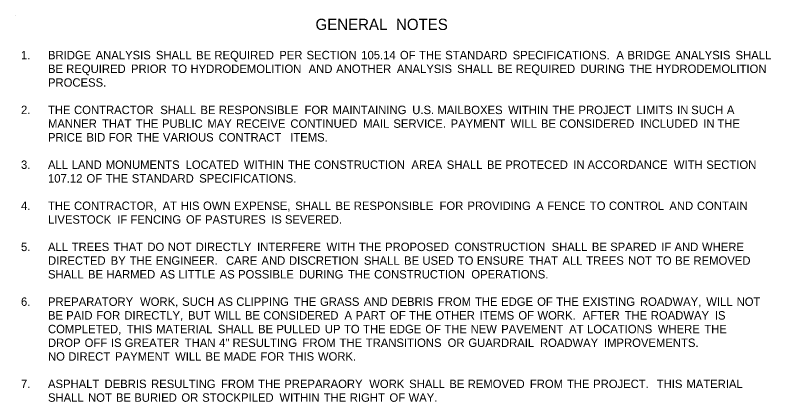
# Model space of a CAD drawing. Extents: x 1930579 to 1935779, y 596313 to 597298.
# Drawn here: x 1934270 to 1934916, y 596918 to 597248 of the extents above; entities that cross this region are included whole.
import ezdxf

# ---------------------------------------------------------------- set-up
doc = ezdxf.new("R2010")
doc.units = 0
doc.layers.add('Default', color=7, linetype='Continuous')
doc.layers.add('R_Border', color=7, linetype='Continuous')

msp = doc.modelspace()

# ---------------------------------------------------------------- linework, layer by layer
at = {"layer": 'R_Border'}
msp.add_line((1934270.13, 597248.45), (1934270.13, 597248.45), dxfattribs=at)

# ---------------------------------------------------------------- texts
at = {"layer": 'Default'}
for s, height, p in [('GENERAL', 9.6, (1934526.75, 597235.75)), (' NOTES', 9.6, (1934591.93, 597235.75)), ('1.', 7.2, (1934275.15, 597210.7)), ('BRIDGE', 7.2, (1934298.21, 597210.7)), (' ANALYSIS', 7.2, (1934336.24, 597210.7)), (' SHALL', 7.2, (1934387.72, 597210.7)), (' BE', 7.2, (1934422.03, 597210.7)), (' REQUIRED', 7.2, (1934437.71, 597210.7)), (' PER', 7.2, (1934493.07, 597210.7)), (' SECTION', 7.2, (1934516.41, 597210.7)), (' 105.14', 7.2, (1934563.1, 597210.7)), (' OF', 7.2, (1934596.16, 597210.7)), (' THE', 7.2, (1934612.47, 597210.7)), (' STANDARD', 7.2, (1934634.85, 597210.7)), (' SPECIFICATIONS.', 7.2, (1934692.45, 597210.7)), (' A', 7.2, (1934781.01, 597210.7)), (' BRIDGE', 7.2, (1934790.53, 597210.7)), (' ANALYSIS', 7.2, (1934831.36, 597210.7)), (' SHALL', 7.2, (1934882.84, 597210.7)), ('BE', 7.2, (1934298.21, 597199)), (' REQUIRED', 7.2, (1934311.09, 597199)), (' PRIOR', 7.2, (1934366.45, 597199)), (' TO', 7.2, (1934400.97, 597199)), (' HYDRODEMOLITION', 7.2, (1934417.29, 597199)), (' AND', 7.2, (1934518.19, 597199)), (' ANOTHER', 7.2, (1934541.69, 597199)), (' ANALYSIS', 7.2, (1934593.54, 597199)), (' SHALL', 7.2, (1934645.02, 597199)), (' BE', 7.2, (1934679.33, 597199)), (' REQUIRED', 7.2, (1934695, 597199)), (' DURING', 7.2, (1934750.37, 597199)), (' THE', 7.2, (1934792.21, 597199)), (' HYDRODEMOLITION', 7.2, (1934814.59, 597199)), ('PROCESS.', 7.2, (1934298.21, 597187.3)), ('2.', 7.2, (1934275.15, 597163.9)), ('THE', 7.2, (1934298.21, 597163.9)), (' CONTRACTOR', 7.2, (1934317.79, 597163.9)), (' SHALL', 7.2, (1934391.44, 597163.9)), (' BE', 7.2, (1934425.75, 597163.9)), (' RESPONSIBLE', 7.2, (1934441.42, 597163.9)), (' FOR', 7.2, (1934514.69, 597163.9)), (' MAINTAINING', 7.2, (1934538.59, 597163.9)), (' U.S.', 7.2, (1934606.7, 597163.9)), (' MAILBOXES', 7.2, (1934628.18, 597163.9)), (' WITHIN', 7.2, (1934688.59, 597163.9)), (' THE', 7.2, (1934726.32, 597163.9)), (' PROJECT', 7.2, (1934748.7, 597163.9)), (' LIMITS', 7.2, (1934798.25, 597163.9)), (' IN', 7.2, (1934832.93, 597163.9)), (' SUCH', 7.2, (1934844.96, 597163.9)), (' A', 7.2, (1934875.45, 597163.9)), ('MANNER', 7.2, (1934298.21, 597152.2)), (' THAT', 7.2, (1934341.67, 597152.2)), (' THE', 7.2, (1934370.53, 597152.2)), (' PUBLIC', 7.2, (1934392.91, 597152.2)), (' MAY', 7.2, (1934431.64, 597152.2)), (' RECEIVE', 7.2, (1934456.16, 597152.2)), (' CONTINUED', 7.2, (1934502.59, 597152.2)), (' MAIL', 7.2, (1934564.65, 597152.2)), (' SERVICE.', 7.2, (1934590.57, 597152.2)), (' PAYMENT', 7.2, (1934639.45, 597152.2)), (' WILL', 7.2, (1934690.67, 597152.2)), (' BE', 7.2, (1934716.58, 597152.2)), (' CONSIDERED', 7.2, (1934732.26, 597152.2)), (' INCLUDED', 7.2, (1934801.6, 597152.2)), (' IN', 7.2, (1934855.28, 597152.2)), (' THE', 7.2, (1934867.31, 597152.2)), ('PRICE', 7.2, (1934298.21, 597140.5)), (' BID', 7.2, (1934328.42, 597140.5)), (' FOR', 7.2, (1934347.45, 597140.5)), (' THE', 7.2, (1934371.34, 597140.5)), (' VARIOUS', 7.2, (1934393.72, 597140.5)), (' CONTRACT', 7.2, (1934441.27, 597140.5)), ('  ITEMS.', 7.2, (1934499.75, 597140.5)), ('3.', 7.2, (1934275.15, 597117.1)), ('ALL', 7.2, (1934298.21, 597117.1)), (' LAND', 7.2, (1934315.75, 597117.1)), (' MONUMENTS', 7.2, (1934344.84, 597117.1)), (' LOCATED', 7.2, (1934413.06, 597117.1)), (' WITHIN', 7.2, (1934462.83, 597117.1)), (' THE', 7.2, (1934500.56, 597117.1)), (' CONSTRUCTION', 7.2, (1934522.94, 597117.1)), (' AREA', 7.2, (1934605.95, 597117.1)), (' SHALL', 7.2, (1934636.16, 597117.1)), (' BE', 7.2, (1934670.47, 597117.1)), (' PROTECED', 7.2, (1934686.15, 597117.1)), (' IN', 7.2, (1934744.31, 597117.1)), (' ACCORDANCE', 7.2, (1934756.34, 597117.1)), (' WITH', 7.2, (1934830.15, 597117.1)), (' SECTION', 7.2, (1934857.83, 597117.1)), ('107.12', 7.2, (1934298.21, 597105.4)), (' OF', 7.2, (1934328.43, 597105.4)), (' THE', 7.2, (1934344.73, 597105.4)), (' STANDARD', 7.2, (1934367.11, 597105.4)), (' SPECIFICATIONS.', 7.2, (1934424.71, 597105.4)), ('4.', 7.2, (1934275.15, 597082)), ('THE', 7.2, (1934298.21, 597082)), (' CONTRACTOR,', 7.2, (1934317.79, 597082)), (' AT', 7.2, (1934393.47, 597082)), (' HIS', 7.2, (1934408.92, 597082)), (' OWN', 7.2, (1934427.96, 597082)), (' EXPENSE,', 7.2, (1934454.51, 597082)), (' SHALL', 7.2, (1934506.74, 597082)), (' BE', 7.2, (1934541.05, 597082)), (' RESPONSIBLE', 7.2, (1934556.73, 597082)), (' FOR', 7.2, (1934630, 597082)), (' PROVIDING', 7.2, (1934653.89, 597082)), (' A', 7.2, (1934712.51, 597082)), (' FENCE', 7.2, (1934722.03, 597082)), (' TO', 7.2, (1934758.39, 597082)), (' CONTROL', 7.2, (1934774.7, 597082)), (' AND', 7.2, (1934826.33, 597082)), (' CONTAIN', 7.2, (1934849.83, 597082)), ('LIVESTOCK', 7.2, (1934298.21, 597070.3)), (' IF', 7.2, (1934354.66, 597070.3)), (' FENCING', 7.2, (1934365.93, 597070.3)), (' OF', 7.2, (1934413.36, 597070.3)), (' PASTURES', 7.2, (1934429.67, 597070.3)), (' IS', 7.2, (1934486.17, 597070.3)), (' SEVERED.', 7.2, (1934497.94, 597070.3)), ('5.', 7.2, (1934275.15, 597046.9)), ('ALL', 7.2, (1934298.21, 597046.9)), (' TREES', 7.2, (1934315.75, 597046.9)), (' THAT', 7.2, (1934351.56, 597046.9)), (' DO', 7.2, (1934380.42, 597046.9)), (' NOT', 7.2, (1934397.86, 597046.9)), (' DIRECTLY', 7.2, (1934421.68, 597046.9)), (' INTERFERE', 7.2, (1934474.15, 597046.9)), (' WITH', 7.2, (1934533.43, 597046.9)), (' THE', 7.2, (1934561.11, 597046.9)), (' PROPOSED', 7.2, (1934583.49, 597046.9)), (' CONSTRUCTION', 7.2, (1934642.77, 597046.9)), (' SHALL', 7.2, (1934725.79, 597046.9)), (' BE', 7.2, (1934760.1, 597046.9)), (' SPARED', 7.2, (1934775.77, 597046.9)), (' IF', 7.2, (1934819.41, 597046.9)), (' AND', 7.2, (1934830.68, 597046.9)), (' WHERE', 7.2, (1934854.18, 597046.9)), ('DIRECTED', 7.2, (1934298.21, 597035.2)), (' BY', 7.2, (1934349.1, 597035.2)), (' THE', 7.2, (1934365.24, 597035.2)), (' ENGINEER.', 7.2, (1934387.62, 597035.2)), ('  CARE', 7.2, (1934444.88, 597035.2)), (' AND', 7.2, (1934477.88, 597035.2)), (' DISCRETION', 7.2, (1934501.38, 597035.2)), (' SHALL', 7.2, (1934565.39, 597035.2)), (' BE', 7.2, (1934599.7, 597035.2)), (' USED', 7.2, (1934615.38, 597035.2)), (' TO', 7.2, (1934645.59, 597035.2)), (' ENSURE', 7.2, (1934661.91, 597035.2)), (' THAT', 7.2, (1934706.1, 597035.2)), (' ALL', 7.2, (1934734.96, 597035.2)), (' TREES', 7.2, (1934755.29, 597035.2)), (' NOT', 7.2, (1934791.1, 597035.2)), (' TO', 7.2, (1934814.93, 597035.2)), (' BE', 7.2, (1934831.24, 597035.2)), (' REMOVED', 7.2, (1934846.92, 597035.2)), ('SHALL', 7.2, (1934298.21, 597023.5)), (' BE', 7.2, (1934329.73, 597023.5)), (' HARMED', 7.2, (1934345.4, 597023.5)), (' AS', 7.2, (1934391.26, 597023.5)), (' LITTLE', 7.2, (1934406.95, 597023.5)), (' AS', 7.2, (1934442.19, 597023.5)), (' POSSIBLE', 7.2, (1934457.88, 597023.5)), (' DURING', 7.2, (1934509.9, 597023.5)), (' THE', 7.2, (1934551.75, 597023.5)), (' CONSTRUCTION', 7.2, (1934574.12, 597023.5)), (' OPERATIONS.', 7.2, (1934657.14, 597023.5)), ('6.', 7.2, (1934275.15, 597000.1)), ('PREPARATORY', 7.2, (1934298.21, 597000.1)), (' WORK,', 7.2, (1934374.17, 597000.1)), (' SUCH', 7.2, (1934410.16, 597000.1)), (' AS', 7.2, (1934440.65, 597000.1)), (' CLIPPING', 7.2, (1934456.34, 597000.1)), (' THE', 7.2, (1934505.46, 597000.1)), (' GRASS', 7.2, (1934527.84, 597000.1)), (' AND', 7.2, (1934565.33, 597000.1)), (' DEBRIS', 7.2, (1934588.83, 597000.1)), (' FROM', 7.2, (1934628.56, 597000.1)), (' THE', 7.2, (1934660.21, 597000.1)), (' EDGE', 7.2, (1934682.59, 597000.1)), (' OF', 7.2, (1934713.36, 597000.1)), (' THE', 7.2, (1934729.67, 597000.1)), (' EXISTING', 7.2, (1934752.04, 597000.1)), (' ROADWAY,', 7.2, (1934801.17, 597000.1)), (' WILL', 7.2, (1934857.84, 597000.1)), (' NOT', 7.2, (1934883.75, 597000.1)), ('BE', 7.2, (1934298.21, 596988.4)), (' PAID', 7.2, (1934311.09, 596988.4)), (' FOR', 7.2, (1934336.83, 596988.4)), (' DIRECTLY,', 7.2, (1934360.73, 596988.4)), (' BUT', 7.2, (1934415.17, 596988.4)), (' WILL', 7.2, (1934437.88, 596988.4)), (' BE', 7.2, (1934463.79, 596988.4)), (' CONSIDERED', 7.2, (1934479.47, 596988.4)), (' A', 7.2, (1934548.81, 596988.4)), (' PART', 7.2, (1934558.33, 596988.4)), (' OF', 7.2, (1934587.76, 596988.4)), (' THE', 7.2, (1934604.06, 596988.4)), (' OTHER', 7.2, (1934626.44, 596988.4)), (' ITEMS', 7.2, (1934664.31, 596988.4)), (' OF', 7.2, (1934697.32, 596988.4)), (' WORK.', 7.2, (1934713.62, 596988.4)), ('  AFTER', 7.2, (1934749.63, 596988.4)), (' THE', 7.2, (1934788.06, 596988.4)), (' ROADWAY', 7.2, (1934810.44, 596988.4)), (' IS', 7.2, (1934865.14, 596988.4)), ('COMPLETED,', 7.2, (1934298.21, 596976.7)), (' THIS', 7.2, (1934362.72, 596976.7)), (' MATERIAL', 7.2, (1934387.9, 596976.7)), (' SHALL', 7.2, (1934440.65, 596976.7)), (' BE', 7.2, (1934474.96, 596976.7)), (' PULLED', 7.2, (1934490.64, 596976.7)), (' UP', 7.2, (1934532.03, 596976.7)), (' TO', 7.2, (1934548.36, 596976.7)), (' THE', 7.2, (1934564.68, 596976.7)), (' EDGE', 7.2, (1934587.06, 596976.7)), (' OF', 7.2, (1934617.83, 596976.7)), (' THE', 7.2, (1934634.13, 596976.7)), (' NEW', 7.2, (1934656.51, 596976.7)), (' PAVEMENT', 7.2, (1934682.66, 596976.7)), (' AT', 7.2, (1934740.6, 596976.7)), (' LOCATIONS', 7.2, (1934756.05, 596976.7)), (' WHERE', 7.2, (1934816.45, 596976.7)), (' THE', 7.2, (1934856.16, 596976.7)), ('DROP', 7.2, (1934298.21, 596965)), (' OFF', 7.2, (1934326.84, 596965)), (' IS', 7.2, (1934349.29, 596965)), (' GREATER', 7.2, (1934361.06, 596965)), (' THAN', 7.2, (1934412.35, 596965)), (' 4"', 7.2, (1934441.71, 596965)), (' RESULTING', 7.2, (1934453.2, 596965)), (' FROM', 7.2, (1934512.94, 596965)), (' THE', 7.2, (1934544.59, 596965)), (' TRANSITIONS', 7.2, (1934566.97, 596965)), (' OR', 7.2, (1934636.88, 596965)), (' GUARDRAIL', 7.2, (1934654.63, 596965)), (' ROADWAY', 7.2, (1934715.76, 596965)), (' IMPROVEMENTS.', 7.2, (1934770.46, 596965)), ('NO', 7.2, (1934298.21, 596953.3)), (' DIRECT', 7.2, (1934312.85, 596953.3)), (' PAYMENT', 7.2, (1934352.89, 596953.3)), (' WILL', 7.2, (1934404.12, 596953.3)), (' BE', 7.2, (1934430.03, 596953.3)), (' MADE', 7.2, (1934445.7, 596953.3)), (' FOR', 7.2, (1934477.03, 596953.3)), (' THIS', 7.2, (1934500.92, 596953.3)), (' WORK.', 7.2, (1934526.11, 596953.3)), ('7.', 7.2, (1934275.15, 596929.9)), ('ASPHALT', 7.2, (1934298.21, 596929.9)), (' DEBRIS', 7.2, (1934343.86, 596929.9)), (' RESULTING', 7.2, (1934383.58, 596929.9)), (' FROM', 7.2, (1934443.32, 596929.9)), (' THE', 7.2, (1934474.98, 596929.9)), (' PREPARAORY', 7.2, (1934497.36, 596929.9)), (' WORK', 7.2, (1934569.96, 596929.9)), (' SHALL', 7.2, (1934604.03, 596929.9)), (' BE', 7.2, (1934638.34, 596929.9)), (' REMOVED', 7.2, (1934654.02, 596929.9)), (' FROM', 7.2, (1934707.15, 596929.9)), (' THE', 7.2, (1934738.8, 596929.9)), (' PROJECT.', 7.2, (1934761.18, 596929.9)), ('  THIS', 7.2, (1934812.85, 596929.9)), (' MATERIAL', 7.2, (1934840.83, 596929.9)), ('SHALL', 7.2, (1934298.21, 596918.2)), (' NOT', 7.2, (1934329.73, 596918.2)), (' BE', 7.2, (1934353.55, 596918.2)), (' BURIED', 7.2, (1934369.23, 596918.2)), (' OR', 7.2, (1934409.5, 596918.2)), (' STOCKPILED', 7.2, (1934427.25, 596918.2)), (' WITHIN', 7.2, (1934493.24, 596918.2)), (' THE', 7.2, (1934530.97, 596918.2)), (' RIGHT', 7.2, (1934553.35, 596918.2)), (' OF', 7.2, (1934587.23, 596918.2)), (' WAY.', 7.2, (1934603.54, 596918.2))]:
    msp.add_text(s, height=height, dxfattribs=at).set_placement(p)

doc.saveas('drawing.dxf')
